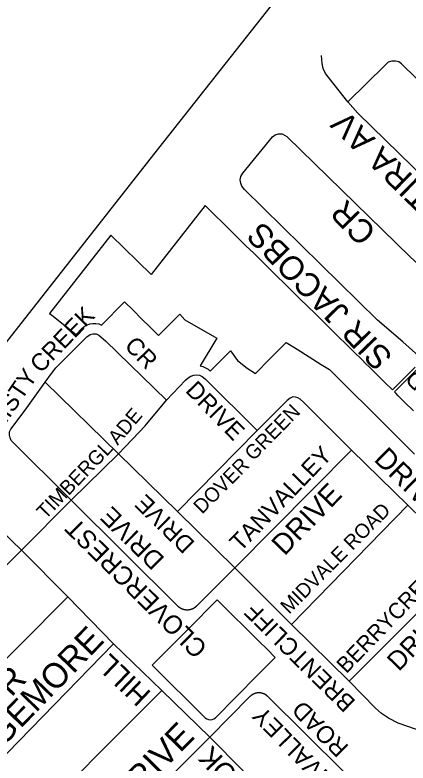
# Model space of a CAD drawing. Extents: x 586326 to 623965, y 4819854 to 4857850.
# Drawn here: x 594121 to 594531, y 4839802 to 4840582 of the extents above; entities that cross this region are included whole.
import ezdxf

# ---------------------------------------------------------------- set-up
doc = ezdxf.new("R2010")
doc.units = 0
for name, color, linetype in [('Major Rds and Hwys', 7, 'Continuous'), ('Minor Rd Lbls', 7, 'Continuous'), ('Minor Rds', 7, 'Continuous'), ('Park Outlines', 7, 'Continuous'), ('Proposed Secondary Rds', 7, 'Continuous'), ('Secondary Rds Lbls', 7, 'Continuous')]:
    doc.layers.add(name, color=color, linetype=linetype)

msp = doc.modelspace()

# ---------------------------------------------------------------- linework, layer by layer
at = {"layer": 'Major Rds and Hwys'}
for points in [[(594469.15, 4840694.43), (594265.69, 4840436.23)], [(594265.69, 4840436.23), (594052.25, 4840164.95), (594052.12, 4840164.79), (594017.28, 4840120.53)]]:
    msp.add_lwpolyline(points, dxfattribs=at)
at = {"layer": 'Minor Rds'}
for points in [[(594468.26, 4840491.12), (594444.8, 4840520.66), (594442.31, 4840525.81), (594441.25, 4840531.07), (594440.72, 4840539.38)], [(594670.53, 4840399.32), (594640.81, 4840418.85), (594630.03, 4840427.46), (594524.22, 4840530.78), (594521.38, 4840532.81), (594517.85, 4840533.72), (594514.13, 4840533.68), (594510.24, 4840532.48), (594506.95, 4840529.36), (594468.26, 4840491.12)], [(594631.2, 4840342.55), (594606.64, 4840358.56), (594591.15, 4840370.66), (594578.56, 4840381.99), (594478.57, 4840479.44), (594468.26, 4840491.12)], [(594545.2, 4840223.5), (594525.47, 4840240.98), (594499.1, 4840263.65), (594360.44, 4840399.93), (594357.81, 4840403.29), (594356.46, 4840406.6), (594355.94, 4840410.01), (594356.57, 4840413.46), (594358.65, 4840417.08), (594389.61, 4840454.79), (594392.4, 4840456.92), (594395.85, 4840457.98), (594399.75, 4840457.93), (594404.4, 4840455.24), (594533.17, 4840329.85), (594541.43, 4840322.21), (594551.05, 4840314.3), (594590.07, 4840285.98)], [(594152.74, 4840199.18), (594159.29, 4840208.29), (594163.71, 4840213.95), (594168.8, 4840219.37), (594196.13, 4840246.52), (594199.38, 4840248.68), (594202.23, 4840249.59), (594205.68, 4840249.45), (594208.55, 4840248.21), (594215.43, 4840242.26), (594279, 4840180.5)], [(594279, 4840180.5), (594298.9, 4840201.23), (594301.87, 4840203.75), (594304.63, 4840205.29), (594307.68, 4840206.47), (594310.69, 4840206.68), (594313.38, 4840206.29), (594316.42, 4840204.9), (594319.56, 4840202.73), (594373.7, 4840148.92)], [(594179.6, 4840076.29), (594117.25, 4840138.27), (594116.03, 4840141.08), (594115.35, 4840144.03), (594115.59, 4840147.26), (594116.83, 4840150.12), (594131.96, 4840170.03), (594152.74, 4840199.18)], [(594228.92, 4840124.59), (594152.74, 4840199.18)], [(594228.92, 4840124.59), (594250.69, 4840146.99), (594256.97, 4840153.75), (594279, 4840180.5)], [(594471.98, 4840128.32), (594421.91, 4840178.4), (594418.59, 4840181.42), (594416.01, 4840182.87), (594413.61, 4840183.61), (594410.87, 4840183.75), (594408.07, 4840182.53), (594404.94, 4840179.99), (594373.7, 4840148.92)], [(594290.72, 4840064.21), (594373.7, 4840148.92)], [(594179.6, 4840076.29), (594228.92, 4840124.59)], [(594290.72, 4840064.21), (594228.92, 4840124.59)], [(594350.47, 4840005.76), (594471.98, 4840128.32)], [(594530.79, 4840070.99), (594471.98, 4840128.32)], [(594127.8, 4840023.97), (594179.6, 4840076.29)], [(594350.47, 4840005.76), (594310.28, 4839965.61), (594310.21, 4839965.53), (594310.14, 4839965.46), (594310.07, 4839965.39), (594309.99, 4839965.32), (594309.92, 4839965.25), (594309.84, 4839965.19), (594309.77, 4839965.12), (594309.69, 4839965.05), (594309.62, 4839964.98), (594309.54, 4839964.92), (594309.46, 4839964.85), (594309.39, 4839964.78), (594309.31, 4839964.72), (594309.23, 4839964.66), (594309.15, 4839964.59), (594309.07, 4839964.53), (594308.99, 4839964.47), (594308.91, 4839964.4), (594308.83, 4839964.34), (594308.75, 4839964.28), (594308.66, 4839964.22), (594308.58, 4839964.16), (594308.5, 4839964.1), (594308.42, 4839964.05), (594308.33, 4839963.99), (594308.25, 4839963.93), (594308.16, 4839963.88), (594308.08, 4839963.82), (594307.99, 4839963.77), (594307.91, 4839963.71), (594307.82, 4839963.66), (594307.73, 4839963.6), (594307.65, 4839963.55), (594307.56, 4839963.5), (594307.47, 4839963.45), (594307.38, 4839963.4), (594307.3, 4839963.35), (594307.21, 4839963.3), (594307.12, 4839963.25), (594307.03, 4839963.2), (594306.94, 4839963.16), (594306.85, 4839963.11), (594306.76, 4839963.06), (594306.67, 4839963.02), (594306.57, 4839962.97), (594306.48, 4839962.93), (594306.39, 4839962.89), (594306.3, 4839962.84), (594306.21, 4839962.8), (594306.11, 4839962.76), (594306.02, 4839962.72), (594305.93, 4839962.68), (594305.83, 4839962.64), (594305.74, 4839962.6), (594305.64, 4839962.57), (594305.55, 4839962.53), (594305.45, 4839962.49), (594305.36, 4839962.46), (594305.26, 4839962.42), (594305.17, 4839962.39), (594305.07, 4839962.36), (594304.98, 4839962.32), (594304.88, 4839962.29), (594304.78, 4839962.26), (594304.69, 4839962.23), (594304.59, 4839962.2), (594304.49, 4839962.17), (594304.39, 4839962.14), (594304.3, 4839962.12), (594304.2, 4839962.09), (594304.1, 4839962.06), (594304, 4839962.04), (594303.9, 4839962.01), (594303.8, 4839961.99), (594303.71, 4839961.97), (594303.61, 4839961.95), (594303.51, 4839961.92), (594303.41, 4839961.9), (594303.31, 4839961.88), (594303.21, 4839961.86), (594303.11, 4839961.84), (594303.01, 4839961.83), (594302.91, 4839961.81), (594302.81, 4839961.79), (594302.71, 4839961.78), (594302.61, 4839961.76), (594302.51, 4839961.75), (594302.41, 4839961.74), (594302.31, 4839961.72), (594302.2, 4839961.71), (594302.1, 4839961.7), (594302, 4839961.69), (594301.9, 4839961.68), (594301.8, 4839961.67), (594301.7, 4839961.66), (594301.6, 4839961.66), (594301.5, 4839961.65), (594301.39, 4839961.64), (594301.29, 4839961.64), (594301.19, 4839961.63), (594301.09, 4839961.63), (594300.99, 4839961.63), (594300.89, 4839961.63), (594300.79, 4839961.62), (594300.68, 4839961.62), (594300.58, 4839961.62), (594300.48, 4839961.62), (594300.38, 4839961.63), (594300.28, 4839961.63), (594300.18, 4839961.63), (594300.07, 4839961.64), (594299.97, 4839961.64), (594299.87, 4839961.65), (594299.77, 4839961.65), (594299.67, 4839961.66), (594299.57, 4839961.67), (594299.47, 4839961.68), (594299.37, 4839961.69), (594299.26, 4839961.7), (594299.16, 4839961.71), (594299.06, 4839961.72), (594298.96, 4839961.73), (594298.86, 4839961.74), (594298.76, 4839961.76), (594298.66, 4839961.77), (594298.56, 4839961.79), (594298.46, 4839961.8), (594298.36, 4839961.82), (594298.26, 4839961.84), (594298.16, 4839961.86), (594298.06, 4839961.87), (594297.96, 4839961.89), (594297.86, 4839961.92), (594297.76, 4839961.94), (594297.66, 4839961.96), (594297.56, 4839961.98), (594297.46, 4839962), (594297.37, 4839962.03), (594297.27, 4839962.05), (594297.17, 4839962.08), (594297.07, 4839962.11), (594296.97, 4839962.13), (594296.87, 4839962.16), (594296.78, 4839962.19), (594296.68, 4839962.22), (594296.58, 4839962.25), (594296.49, 4839962.28), (594296.39, 4839962.31), (594296.29, 4839962.34), (594296.2, 4839962.38), (594296.1, 4839962.41), (594296.01, 4839962.44), (594295.91, 4839962.48), (594295.82, 4839962.52), (594295.72, 4839962.55), (594295.63, 4839962.59), (594295.53, 4839962.63), (594295.44, 4839962.67), (594295.34, 4839962.71), (594295.25, 4839962.75), (594295.16, 4839962.79), (594295.07, 4839962.83), (594294.97, 4839962.87), (594294.88, 4839962.91), (594294.79, 4839962.96), (594294.7, 4839963), (594294.61, 4839963.04), (594294.52, 4839963.09), (594294.43, 4839963.14), (594294.34, 4839963.18), (594294.25, 4839963.23), (594294.16, 4839963.28), (594294.07, 4839963.33), (594293.98, 4839963.38), (594293.89, 4839963.43), (594293.8, 4839963.48), (594293.71, 4839963.53), (594293.63, 4839963.58), (594293.54, 4839963.64), (594293.45, 4839963.69), (594293.37, 4839963.74), (594293.28, 4839963.8), (594293.2, 4839963.85), (594293.11, 4839963.91), (594293.03, 4839963.97), (594292.94, 4839964.02), (594292.86, 4839964.08), (594292.78, 4839964.14), (594292.7, 4839964.2), (594292.61, 4839964.26), (594292.53, 4839964.32), (594292.45, 4839964.38), (594292.37, 4839964.44), (594292.29, 4839964.5), (594292.21, 4839964.57), (594292.13, 4839964.63), (594292.05, 4839964.69), (594291.97, 4839964.76), (594291.89, 4839964.82), (594291.82, 4839964.89), (594291.74, 4839964.96), (594291.66, 4839965.02), (594291.59, 4839965.09), (594291.51, 4839965.16), (594291.44, 4839965.23), (594291.36, 4839965.3), (594291.29, 4839965.36), (594291.22, 4839965.44), (594291.14, 4839965.51), (594291.07, 4839965.58), (594179.6, 4840076.29)], [(594409.52, 4839946.75), (594530.79, 4840070.99)], [(594584.49, 4840002.37), (594572.12, 4840015.9), (594567.86, 4840021.5), (594554.27, 4840043.93), (594550.81, 4840050.27), (594546.19, 4840055.69), (594530.79, 4840070.99)], [(594350.47, 4840005.76), (594290.72, 4840064.21)], [(594076.12, 4839972.26), (594127.8, 4840023.97)], [(594409.52, 4839946.75), (594350.47, 4840005.76)], [(594584.49, 4840002.37), (594469.51, 4839887.42)], [(594075.98, 4839874.67), (594176.18, 4839975.44)], [(594469.51, 4839887.42), (594409.52, 4839946.75)], [(594076.02, 4839774.62), (594223.94, 4839926.37)], [(594565.83, 4839827.98), (594520.7, 4839843.9), (594510.52, 4839848.92), (594503.3, 4839853.98), (594497.02, 4839859.47), (594469.51, 4839887.42)], [(594274.14, 4839877.87), (594122.53, 4839725.74)], [(594463.83, 4839793), (594384.7, 4839871.55), (594384.63, 4839871.62), (594384.56, 4839871.69), (594384.48, 4839871.76), (594384.41, 4839871.83), (594384.34, 4839871.9), (594384.27, 4839871.97), (594384.19, 4839872.03), (594384.12, 4839872.1), (594384.04, 4839872.16), (594383.97, 4839872.23), (594383.89, 4839872.29), (594383.81, 4839872.36), (594383.74, 4839872.42), (594383.66, 4839872.48), (594383.58, 4839872.54), (594383.5, 4839872.61), (594383.42, 4839872.67), (594383.34, 4839872.73), (594383.26, 4839872.79), (594383.18, 4839872.85), (594383.1, 4839872.9), (594383.02, 4839872.96), (594382.94, 4839873.02), (594382.86, 4839873.08), (594382.78, 4839873.13), (594382.69, 4839873.19), (594382.61, 4839873.24), (594382.53, 4839873.3), (594382.44, 4839873.35), (594382.36, 4839873.4), (594382.27, 4839873.45), (594382.19, 4839873.51), (594382.1, 4839873.56), (594382.01, 4839873.61), (594381.93, 4839873.66), (594381.84, 4839873.7), (594381.75, 4839873.75), (594381.67, 4839873.8), (594381.58, 4839873.85), (594381.49, 4839873.89), (594381.4, 4839873.94), (594381.31, 4839873.98), (594381.22, 4839874.03), (594381.13, 4839874.07), (594381.04, 4839874.11), (594380.95, 4839874.16), (594380.86, 4839874.2), (594380.77, 4839874.24), (594380.68, 4839874.28), (594380.59, 4839874.32), (594380.5, 4839874.36), (594380.4, 4839874.39), (594380.31, 4839874.43), (594380.22, 4839874.47), (594380.13, 4839874.5), (594380.03, 4839874.54), (594379.94, 4839874.57), (594379.85, 4839874.61), (594379.75, 4839874.64), (594379.66, 4839874.67), (594379.56, 4839874.7), (594379.47, 4839874.73), (594379.37, 4839874.76), (594379.28, 4839874.79), (594379.18, 4839874.82), (594379.09, 4839874.85), (594378.99, 4839874.88), (594378.89, 4839874.9), (594378.8, 4839874.93), (594378.7, 4839874.95), (594378.6, 4839874.98), (594378.51, 4839875), (594378.41, 4839875.03), (594378.31, 4839875.05), (594378.22, 4839875.07), (594378.12, 4839875.09), (594378.02, 4839875.11), (594377.92, 4839875.13), (594377.83, 4839875.15), (594377.73, 4839875.16), (594377.63, 4839875.18), (594377.53, 4839875.2), (594377.43, 4839875.21), (594377.33, 4839875.23), (594377.23, 4839875.24), (594377.14, 4839875.25), (594377.04, 4839875.27), (594376.94, 4839875.28), (594376.84, 4839875.29), (594376.74, 4839875.3), (594376.64, 4839875.31), (594376.54, 4839875.32), (594376.44, 4839875.33), (594376.34, 4839875.33), (594376.24, 4839875.34), (594376.14, 4839875.34), (594376.04, 4839875.35), (594375.94, 4839875.35), (594375.84, 4839875.36), (594375.75, 4839875.36), (594375.65, 4839875.36), (594375.55, 4839875.36), (594375.45, 4839875.36), (594375.35, 4839875.36), (594375.25, 4839875.36), (594375.15, 4839875.36), (594375.05, 4839875.36), (594374.95, 4839875.35), (594374.85, 4839875.35), (594374.75, 4839875.34), (594374.65, 4839875.34), (594374.55, 4839875.33), (594374.45, 4839875.32), (594374.35, 4839875.32), (594374.25, 4839875.31), (594374.15, 4839875.3), (594374.05, 4839875.29), (594373.95, 4839875.28), (594373.86, 4839875.26), (594373.76, 4839875.25), (594373.66, 4839875.24), (594373.56, 4839875.22), (594373.46, 4839875.21), (594373.36, 4839875.19), (594373.26, 4839875.18), (594373.17, 4839875.16), (594373.07, 4839875.14), (594372.97, 4839875.12), (594372.87, 4839875.1), (594372.77, 4839875.08), (594372.68, 4839875.06), (594372.58, 4839875.04), (594372.48, 4839875.02), (594372.39, 4839875), (594372.29, 4839874.97), (594372.19, 4839874.95), (594372.1, 4839874.92), (594372, 4839874.9), (594371.9, 4839874.87), (594371.81, 4839874.84), (594371.71, 4839874.82), (594371.62, 4839874.79), (594371.52, 4839874.76), (594371.43, 4839874.73), (594371.33, 4839874.7), (594371.24, 4839874.66), (594371.14, 4839874.63), (594371.05, 4839874.6), (594370.95, 4839874.57), (594370.86, 4839874.53), (594370.77, 4839874.5), (594370.67, 4839874.46), (594370.58, 4839874.42), (594370.49, 4839874.39), (594370.4, 4839874.35), (594370.31, 4839874.31), (594370.21, 4839874.27), (594370.12, 4839874.23), (594370.03, 4839874.19), (594369.94, 4839874.15), (594369.85, 4839874.1), (594369.76, 4839874.06), (594369.67, 4839874.02), (594369.58, 4839873.97), (594369.49, 4839873.93), (594369.41, 4839873.88), (594369.32, 4839873.84), (594369.23, 4839873.79), (594369.14, 4839873.74), (594369.05, 4839873.69), (594368.97, 4839873.64), (594368.88, 4839873.59), (594368.79, 4839873.54), (594368.71, 4839873.49), (594368.62, 4839873.44), (594368.54, 4839873.39), (594368.45, 4839873.34), (594368.37, 4839873.28), (594368.29, 4839873.23), (594368.2, 4839873.17), (594368.12, 4839873.12), (594368.04, 4839873.06), (594367.96, 4839873.01), (594367.87, 4839872.95), (594367.79, 4839872.89), (594367.71, 4839872.83), (594367.63, 4839872.77), (594367.55, 4839872.71), (594367.47, 4839872.65), (594367.39, 4839872.59), (594367.32, 4839872.53), (594367.24, 4839872.47), (594367.16, 4839872.41), (594367.08, 4839872.34), (594367.01, 4839872.28), (594366.93, 4839872.21), (594366.86, 4839872.15), (594366.78, 4839872.08), (594366.71, 4839872.02), (594366.63, 4839871.95), (594366.56, 4839871.88), (594366.49, 4839871.81), (594366.41, 4839871.75), (594366.34, 4839871.68), (594366.27, 4839871.61), (594366.2, 4839871.54), (594366.13, 4839871.47), (594324.44, 4839829.3)], [(594273, 4839777.69), (594324.44, 4839829.3)]]:
    msp.add_lwpolyline(points, dxfattribs=at)
at = {"layer": 'Park Outlines'}
for points in [[(594538.15, 4840214.78), (594514.55, 4840191.03), (594506.61, 4840198.91), (594498.61, 4840206.86), (594490.61, 4840214.81), (594487.03, 4840218.37), (594482.59, 4840222.73), (594474.55, 4840230.64), (594466.51, 4840238.55), (594458.47, 4840246.45), (594450.43, 4840254.36), (594442.39, 4840262.27), (594434.35, 4840270.17), (594426.31, 4840278.08), (594418.26, 4840285.99), (594410.22, 4840293.89), (594402.18, 4840301.8), (594394.14, 4840309.71), (594386.1, 4840317.61), (594378.06, 4840325.52), (594370.02, 4840333.43), (594361.98, 4840341.33), (594353.94, 4840349.24), (594345.9, 4840357.15), (594337.86, 4840365.05), (594329.82, 4840372.96), (594321.78, 4840380.87), (594319.47, 4840383.14), (594300.62, 4840359.19), (594281.83, 4840335.18), (594263.12, 4840311.27), (594221.18, 4840352.42), (594157.11, 4840270.69), (594159.47, 4840268.84), (594184.89, 4840248.9), (594190.96, 4840255.03), (594193.37, 4840257.07), (594196.09, 4840258.66), (594199.05, 4840259.74), (594202.16, 4840260.29), (594205.31, 4840260.3), (594208.41, 4840259.75), (594211.38, 4840258.67), (594235.33, 4840282.85), (594244.21, 4840274.05), (594253.08, 4840265.26), (594261.96, 4840256.47), (594270.84, 4840247.67), (594292.86, 4840269.91), (594298.38, 4840264.16), (594331.47, 4840244.93), (594314.13, 4840216.26), (594317.07, 4840215.46), (594319.85, 4840214.22), (594322.41, 4840212.57), (594324.69, 4840210.55), (594345.79, 4840231.86), (594353.27, 4840221.64), (594363.04, 4840213.76), (594371.89, 4840208.13), (594386.89, 4840223.27), (594404.02, 4840240.56), (594415.15, 4840233.55), (594440.31, 4840217.69), (594448.86, 4840212.3), (594454.59, 4840206.61), (594464.99, 4840196.3), (594475.38, 4840185.99), (594485.78, 4840175.68), (594496.17, 4840165.38), (594506.57, 4840155.06), (594516.97, 4840144.75), (594527.37, 4840134.43), (594537.77, 4840124.12)], [(594536.6, 4840169.12), (594526.88, 4840178.77), (594520.7, 4840184.92), (594518.11, 4840187.49), (594516.67, 4840188.92), (594540.27, 4840212.67)]]:
    msp.add_lwpolyline(points, dxfattribs=at)
msp.add_lwpolyline([(594331.81, 4839972.35), (594301.56, 4839941.8), (594283.27, 4839923.33), (594264.27, 4839904.16), (594319.5, 4839849.45), (594321.05, 4839848.27), (594322.87, 4839847.53), (594324.81, 4839847.28), (594326.75, 4839847.55), (594328.55, 4839848.31), (594330.1, 4839849.51), (594374.06, 4839893.9), (594392.35, 4839912.37), (594383.9, 4839920.74), (594375.45, 4839929.12), (594367, 4839937.49), (594358.55, 4839945.86), (594350.1, 4839954.23), (594341.64, 4839962.6)], close=True, dxfattribs=at)
at = {"layer": 'Proposed Secondary Rds'}
for points in [[(594127.8, 4840023.97), (594085.24, 4840064.95), (594047.49, 4840097.96), (594017.28, 4840120.53)], [(594176.18, 4839975.44), (594127.8, 4840023.97)], [(594223.94, 4839926.37), (594176.18, 4839975.44)], [(594274.14, 4839877.87), (594223.94, 4839926.37)], [(594324.44, 4839829.3), (594274.14, 4839877.87)], [(594507.76, 4839679.96), (594465.18, 4839699.16), (594447.42, 4839709.51), (594435.91, 4839717.34), (594426.99, 4839725.48), (594324.44, 4839829.3)]]:
    msp.add_lwpolyline(points, dxfattribs=at)

# ---------------------------------------------------------------- texts
at = {"layer": 'Minor Rd Lbls'}
for s, height, rotation, p in [('ATIRA AV', 24.797, 135.53093, (594573.87, 4840377.97)), ('CR', 24.797, 134.2395, (594499.23, 4840356.54)), ('SIR JACOBS', 24.797, 134.2395, (594516.14, 4840226.41)), ('CREEK', 18, 45.97672, (594147.97, 4840207.57)), ('CR', 18, 314.28009, (594234.33, 4840236.04)), ('MISTY', 18, 55.77003, (594103.97, 4840144.24)), ('RD', 17.735, 139.15448, (594563.95, 4840191)), ('DRIVE', 18, 314.28901, (594297.91, 4840189.54)), ('ADE', 15, 49.63684, (594228.21, 4840132.67)), ('GREEN', 15, 45.47859, (594369.66, 4840116.37)), ('TIMBERGL', 15, 45.97672, (594152.98, 4840055.4)), ('TANVALLEY', 18, 45.97672, (594356.26, 4840021.6)), ('DRIVE', 21.6, 315.42833, (594494.3, 4840117.79)), ('DOVER', 15, 45.0169, (594316.17, 4840060.97)), ('DRIVE', 21.6, 45.97672, (594402.1, 4840017.34)), ('BRENTCLIFF             DRIVE', 18, 135.37788, (594477.28, 4839866.56)), ('DRIVE', 19.246, 135.37788, (594278.11, 4840015.56)), ('MIDVALE ROAD', 15, 45.1773, (594406.92, 4839956.78)), ('CLOVERCREST ', 19.2456, 135.37788, (594322.93, 4839923.32)), ('BERRYCREEK ', 16.5, 45.97672, (594466.52, 4839894.75)), ('DRIVE', 19.8, 45.97672, (594521.32, 4839896.95)), ('RIDGEMORE', 25.92, 45.97672, (594066.74, 4839775.26)), ('CR', 25.92, 46.52207, (594100.21, 4839852.08)), ('ROAD', 18, 134.83332, (594470.09, 4839819.36)), ('EDENVALLEY', 18, 134.33183, (594490.4, 4839749.7)), ('DRIVE', 25.92, 45.62638, (594235.48, 4839753.02))]:
    msp.add_text(s, height=height, rotation=rotation, dxfattribs=at).set_placement(p)
at = {"layer": 'Secondary Rds Lbls'}
for s, rotation, p in [('HILL      ', 136.40365, (594264.21, 4839875.38)), ('EDENBROOK', 133.13806, (594452.52, 4839686.79))]:
    msp.add_text(s, height=21.6, rotation=rotation, dxfattribs=at).set_placement(p)

doc.saveas('drawing.dxf')
